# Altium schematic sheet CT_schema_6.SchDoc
size 278 x 170 mm
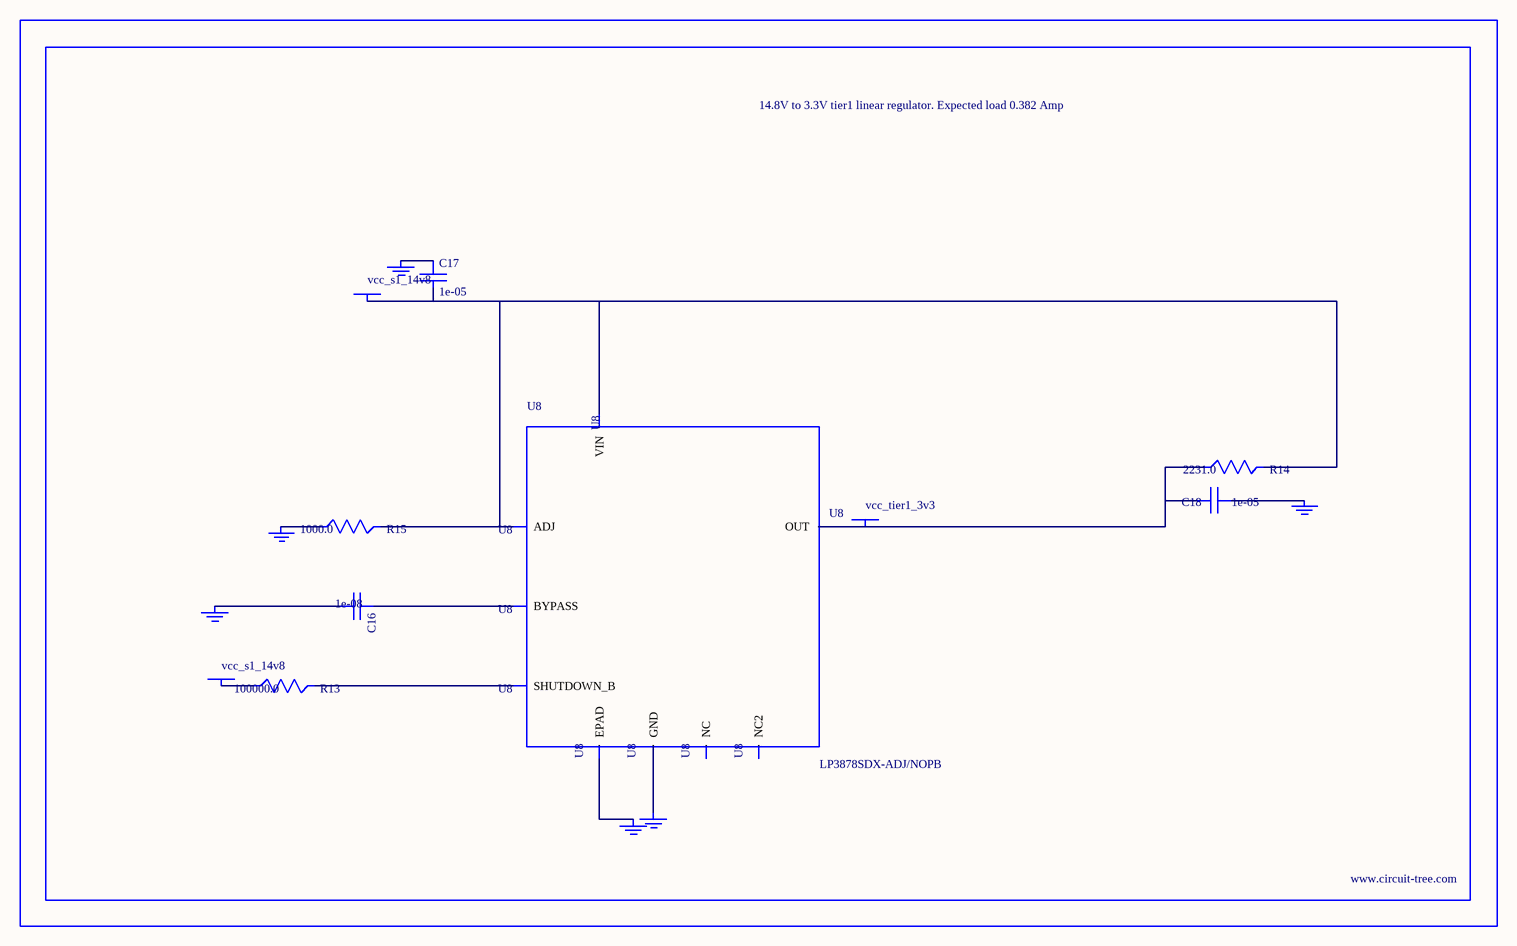
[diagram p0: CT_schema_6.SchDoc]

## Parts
BORDER5  (no value)
C16  1e-08  [C0402]
C17  1e-05  [C1210]
C18  1e-05  [C1210]
GND_INSTANCE_5_0  (no value)
GND_INSTANCE_5_1  (no value)
GND_INSTANCE_5_2  (no value)
GND_INSTANCE_5_3  (no value)
GND_INSTANCE_5_4  (no value)
GND_INSTANCE_5_5  (no value)
POWER_INSTANCE_5_0  vcc_s1_14v8
POWER_INSTANCE_5_1  vcc_s1_14v8
POWER_INSTANCE_5_2  vcc_tier1_3v3
R13  100000.0  [R0603]
R14  2231.0  [R0603]
R15  1000.0  [R0603]
U8  LP3878SDX-ADJ/NOPB  [WSON-8]

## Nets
NetC16_1: C16.1 U8.1(BYPASS)
NetC16_2: C16.2 GND_INSTANCE_5_0.0(GND)
NetC17_1: C17.1 GND_INSTANCE_5_1.0(GND)
NetC17_2: C17.2 POWER_INSTANCE_5_0.0(PWR) R14.2 R15.2 U8.4(VIN) U8.6(ADJ)
NetC18_1: C18.1 GND_INSTANCE_5_2.0(GND)
NetC18_2: C18.2 POWER_INSTANCE_5_2.0(PWR) R14.1 U8.5(OUT)
NetGND_INSTANCE_5_3_0: GND_INSTANCE_5_3.0(GND) R15.1
NetGND_INSTANCE_5_4_0: GND_INSTANCE_5_4.0(GND) U8.PAD(EPAD)
NetGND_INSTANCE_5_5_0: GND_INSTANCE_5_5.0(GND) U8.3(GND)
NetPOWER_INSTANCE_5_1_0: POWER_INSTANCE_5_1.0(PWR) R13.1
NetR13_2: R13.2 U8.8(SHUTDOWN_B)

Not connected (* = marked no-connect by the designer): U8 2(NC) 7(NC2)

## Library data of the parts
BORDER5 = BORDER_PAGE5
C16 = C0402C103K3RAC
C17 = C1210C106K5PACTU
C18 = GRM32DR61E106MA12L
GND_INSTANCE_5_0-GND_INSTANCE_5_5 = GND
POWER_INSTANCE_5_0-POWER_INSTANCE_5_2 = PWR
R13 = RC0603JR-07100KL
R14 = R14
R15 = RC0603JR-071KL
